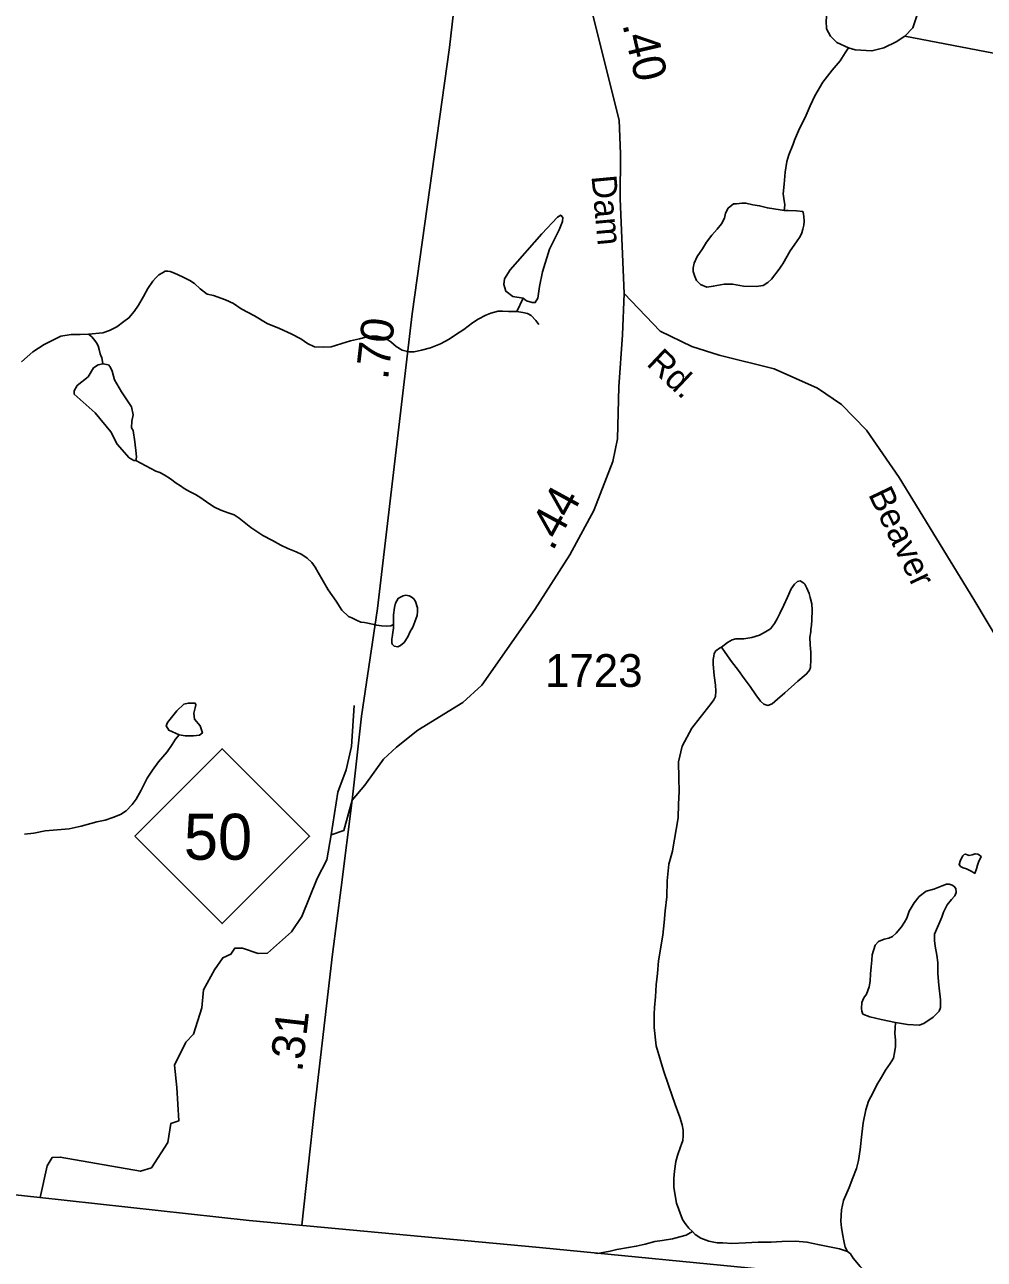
# Model space of a CAD drawing. Extents: x 2056842 to 2160602, y 826753 to 1016856.
# Drawn here: x 2089546 to 2093202, y 846327 to 851032 of the extents above; entities that cross this region are included whole.
import ezdxf

# ---------------------------------------------------------------- set-up
doc = ezdxf.new("R2010")
doc.units = 0
for name, color, linetype in [('Exist Boundary Political CountyLine', 7, 'Continuous'), ('Exist Hydrographic Creek Single Shore', 7, 'Continuous'), ('Exist Hydrographic Misc Water Feature', 7, 'Continuous'), ('Exist Road Non-System Type 51', 7, 'Continuous'), ('Exist Road Primary NC Attributed', 7, 'Continuous'), ('Exist Road Primary NC Service Mileage Hundredths English Label', 7, 'Continuous'), ('Exist Road Primary NC Shield CELL', 7, 'Continuous'), ('Exist Road Primary NC Shield Number Label', 7, 'Continuous'), ('Exist Road Secondary Mileage Hundredths English Label', 7, 'Continuous'), ('Exist Road Secondary Type 20 Attributed', 7, 'Continuous'), ('Exist Road Secondary Type 51 Attributed', 7, 'Continuous'), ('Exist Road Secondary Type 51 Label', 7, 'Continuous'), ('Exist Road Secondary Type 51 Number Label', 7, 'Continuous')]:
    doc.layers.add(name, color=color, linetype=linetype)

msp = doc.modelspace()

# ---------------------------------------------------------------- linework, layer by layer
at = {"layer": 'Exist Boundary Political CountyLine'}
msp.add_lwpolyline([(2087202.4, 846841.6), (2088278.5, 846703.3), (2089060.9, 846620.9), (2089592.9, 846564), (2090401.1, 846475.5), (2091507.2, 846371.9), (2092417.4, 846283.6), (2093037.6, 846221), (2093614.4, 846162.7), (2094823.1, 845562.6), (2096040.2, 844956.3), (2096290.8, 844827.9), (2097736.3, 844110.3), (2098905.5, 843530.6), (2099954.7, 843014.5), (2100389.5, 842806.4), (2101933, 842032.5), (2102162, 841868.8), (2110170.3, 837920.8)], dxfattribs=at)
at = {"layer": 'Exist Hydrographic Creek Single Shore'}
for points in [[(2092899.2, 850987.5), (2093237.1, 850923.1), (2093362.2, 850963.2), (2093719.2, 851313.5), (2093899.2, 851549.4), (2094034.7, 851679.9), (2094262.8, 851850.9)], [(2091421.5, 849938.9), (2091389.1, 849938.6), (2091367, 849940.7), (2091349.6, 849940.5), (2091321.5, 849932.6), (2091303.4, 849924.4), (2091273.5, 849910.2), (2091251.6, 849896.1), (2091219.8, 849870.1), (2091191.7, 849852), (2091163.6, 849834), (2091130, 849816), (2091092, 849799.8), (2091058, 849791.6), (2091029.7, 849785.7), (2091010.2, 849785.5), (2090984, 849791.5), (2090962, 849805.3), (2090941.7, 849823.4), (2090929.8, 849831.3), (2090911.6, 849839.3), (2090889.6, 849845.1), (2090867.5, 849845.2), (2090845.6, 849841.2), (2090821.6, 849835.1), (2090787.5, 849826.9), (2090753.9, 849816.6), (2090729.7, 849808.9), (2090713.7, 849804.8), (2090684, 849802.4), (2090649.9, 849804.3), (2090623.9, 849816.4), (2090597.9, 849834.1), (2090561.8, 849854.2), (2090517.5, 849873.9), (2090469.7, 849893.7), (2090421.3, 849921.8), (2090371.5, 849949.5), (2090341.3, 849969.6), (2090311.4, 849983.4), (2090265.1, 849999.4), (2090241.5, 850005), (2090215.4, 850025.2), (2090193.3, 850045.2), (2090175.2, 850056.8), (2090146.9, 850070.8), (2090117, 850084.7), (2090101, 850090.8), (2090091.2, 850092.7), (2090080.9, 850092.6), (2090070.9, 850086.4), (2090057.3, 850078.4), (2090045, 850066.4), (2090035, 850054.5), (2090015.5, 850026.3), (2089999.5, 849996.2), (2089979.4, 849962.4), (2089963.4, 849938.4), (2089943.7, 849914.2), (2089923.4, 849900.2), (2089897.6, 849880.2), (2089869.9, 849866.1), (2089843.9, 849857.9), (2089789.7, 849851.9)], [(2089789.7, 849851.9), (2089757.8, 849851.5), (2089723.7, 849851.4), (2089683.9, 849845.2), (2089655.8, 849831.2), (2089620, 849813.1), (2089577.9, 849785), (2089534.2, 849747)]]:
    msp.add_lwpolyline(points, dxfattribs=at)
at = {"layer": 'Exist Hydrographic Misc Water Feature'}
msp.add_line((2091444.6, 849989.3), (2091421.5, 849938.9), dxfattribs=at)
for points in [[(2092685, 850943), (2092639.6, 850963.4), (2092615.6, 850987.5), (2092600.4, 851015.4), (2092599.1, 851047), (2092609.2, 851163.6), (2092620.6, 851178.8), (2092647.2, 851187.7), (2092665, 851182.6), (2092711.8, 851156), (2092748.5, 851148.4), (2092785.2, 851148.4), (2092818.2, 851161.1), (2092857.4, 851173.7), (2092894.1, 851172.5), (2092916.9, 851159.8), (2092946, 851116.7), (2092948.6, 851077.5), (2092929.6, 851019.2), (2092899.2, 850987.5)], [(2092899.2, 850987.5), (2092866.3, 850966), (2092819.4, 850943.2), (2092773.8, 850931.8), (2092710.5, 850935.6), (2092685, 850943)], [(2092685, 850943), (2092672, 850924.5), (2092652.5, 850894.6), (2092622.1, 850858.6), (2092586.4, 850812.5), (2092556.5, 850760.2), (2092538.7, 850722.3), (2092519.2, 850678.3), (2092497.3, 850636.1), (2092479.2, 850592.2), (2092473.3, 850576), (2092457.1, 850535.8), (2092449.5, 850509.9), (2092443.5, 850469.8), (2092439.8, 850424.1), (2092435.9, 850387.7), (2092438, 850370), (2092442.1, 850345.8), (2092440, 850323.8)], [(2092440, 850323.8), (2092423.8, 850325.9), (2092375.9, 850333.6), (2092345.7, 850341.8), (2092320.1, 850345.7), (2092293.8, 850351.7), (2092277.6, 850351.2), (2092257.7, 850349.4), (2092245.9, 850349.2), (2092225.8, 850333.2), (2092216.1, 850313.1), (2092212.2, 850295.1), (2092200.1, 850273.4), (2092184.3, 850253), (2092164.2, 850229.3), (2092144.2, 850203.1), (2092128.4, 850177.1), (2092108.5, 850148.9), (2092096.4, 850123.1), (2092092.7, 850105), (2092092.7, 850090.8), (2092098.6, 850072.8), (2092105, 850056.9), (2092121, 850041.1), (2092144.8, 850031), (2092169, 850035.1), (2092211, 850043.3), (2092243, 850043.3), (2092285, 850035.3), (2092333.2, 850033.7), (2092358.8, 850037.9), (2092377.1, 850049.8), (2092390.8, 850061.9), (2092420.6, 850100), (2092430.6, 850115.9), (2092434.7, 850120.2), (2092462.4, 850169.9), (2092486.4, 850204), (2092500.3, 850224.2), (2092506.1, 850238.3), (2092510.2, 850252.3), (2092514.1, 850268.4), (2092516.1, 850282.3), (2092514.3, 850302), (2092511.8, 850316.2), (2092510, 850320.1), (2092486.2, 850322.1), (2092454.2, 850324.1), (2092440, 850323.8)], [(2091444.6, 849989.3), (2091405.4, 849996.5), (2091379.1, 850016.3), (2091371.2, 850041.3), (2091373.8, 850063.7), (2091396.2, 850098), (2091516.1, 850235.1), (2091575.4, 850298.4), (2091588.6, 850306.3), (2091596.5, 850297.1), (2091595.1, 850281.2), (2091582, 850249.6), (2091545.1, 850175.8), (2091518.7, 850090.1), (2091506.9, 850034.7), (2091501.6, 849989.9), (2091491.1, 849972.8), (2091479.2, 849972.8), (2091458.1, 849979.4), (2091444.6, 849989.3)], [(2091505.4, 849888.9), (2091493.7, 849904.9), (2091475.5, 849923), (2091461.3, 849930.9), (2091443.3, 849934.8), (2091421.5, 849938.9)], [(2089844.2, 849739.4), (2089840, 849764), (2089838.1, 849767.9), (2089833.8, 849777.9), (2089830.1, 849793.9), (2089826, 849807.9), (2089820.1, 849819.8), (2089814.1, 849828), (2089802, 849841.9), (2089789.7, 849851.9)], [(2089969.4, 849371.6), (2089961.5, 849371.6), (2089944.4, 849380.9), (2089898.2, 849433.6), (2089874.5, 849479.7), (2089815.2, 849552.2), (2089734.9, 849623.4), (2089734.9, 849636.6), (2089746.7, 849656.4), (2089787.6, 849689.3), (2089808.7, 849723.6), (2089825.8, 849735.5), (2089844.2, 849739.4)], [(2089844.2, 849739.4), (2089865.3, 849735.5), (2089871.9, 849727.6), (2089879.8, 849711.8), (2089889, 849678.8), (2089915.4, 849632.7), (2089953.6, 849576), (2089960.2, 849545.7), (2089954.9, 849520.6), (2089953.6, 849495.6), (2089960.2, 849485), (2089965.4, 849442.8), (2089970.7, 849398), (2089972, 849383.5), (2089969.4, 849371.6)], [(2090950.7, 848745.6), (2090941.1, 848741.3), (2090923.5, 848739.6), (2090905, 848741.5), (2090887.2, 848743.4), (2090859.3, 848749.3), (2090841.2, 848753.3), (2090827.1, 848755), (2090810.9, 848763.1), (2090793.1, 848771.1), (2090779.3, 848776.9), (2090754.7, 848800.8), (2090732.8, 848835), (2090702.6, 848878.5), (2090664.5, 848944.8), (2090652.4, 848964.5), (2090640.5, 848982.5), (2090622.5, 848998.6), (2090602.2, 849012.3), (2090580, 849022.5), (2090548.4, 849036.2), (2090522.2, 849047.9), (2090490, 849066.1), (2090454.1, 849085.8), (2090408.2, 849115.5), (2090363.9, 849151.4), (2090343.8, 849163.4), (2090321.9, 849171.6), (2090293.8, 849181.5), (2090269.8, 849193.3), (2090247.8, 849207.1), (2090217.5, 849229.2), (2090197.4, 849241.1), (2090173.6, 849252.9), (2090153.9, 849264.8), (2090139.4, 849275.1), (2090123.6, 849284.8), (2090101.6, 849300.7), (2090077.4, 849316.6), (2090061.4, 849324.7), (2090045.4, 849330.8), (2089969.4, 849371.6)], [(2092201.2, 848659.5), (2092215.3, 848639.5), (2092239.3, 848605.5), (2092265.5, 848571.4), (2092287.5, 848539.8), (2092309.6, 848509.6), (2092331.6, 848477.9), (2092349.6, 848454.1), (2092361.7, 848442.1), (2092377.5, 848438), (2092393.9, 848444.1), (2092413.8, 848462.2), (2092441.7, 848486.3), (2092491.5, 848530.3), (2092523.5, 848556.3), (2092531.5, 848566.4), (2092535.6, 848572.3), (2092539.3, 848582.7), (2092541.3, 848612.5), (2092541.3, 848640.4), (2092539.1, 848668.3), (2092537, 848698.3), (2092540.7, 848718.4), (2092541.1, 848728.5), (2092543, 848742.4), (2092545, 848764.5), (2092546.7, 848800.3), (2092544.8, 848824.5), (2092538.7, 848848.6), (2092534.4, 848864.6), (2092526.4, 848884.6), (2092518.4, 848900.3), (2092514.3, 848904.2), (2092500.3, 848912.4), (2092490.7, 848910.2), (2092478.4, 848900.3), (2092466.5, 848882.3), (2092452.5, 848850.3), (2092438.6, 848820.3), (2092422.8, 848788.2), (2092412.6, 848768.3), (2092402.7, 848749.9), (2092387.1, 848730), (2092368.9, 848718.1), (2092345.3, 848705.9), (2092316.8, 848696), (2092285.2, 848691.9), (2092254.9, 848691.6), (2092241.1, 848687.6), (2092223.3, 848677.7), (2092205.3, 848663.4), (2092201.2, 848659.5)], [(2090950.7, 848745.6), (2090951, 848731.3), (2090949.1, 848717.4), (2090947.1, 848705.5), (2090945.2, 848689.6), (2090945, 848675.4), (2090947.1, 848669.5), (2090953.4, 848663.6), (2090967.4, 848661.5), (2090977.4, 848665.7), (2090991.3, 848677.8), (2091005.3, 848699.6), (2091014.9, 848719.6), (2091025.2, 848735.9), (2091032.8, 848755.8), (2091041, 848779.8), (2091042.8, 848795.7), (2091043, 848809.9), (2091034.8, 848833.9), (2091028.9, 848843.7), (2091018.6, 848851.8), (2091010.8, 848855.7), (2090998.7, 848857.6), (2090988.7, 848855.4), (2090974.9, 848849.4), (2090968.8, 848845.5), (2090958.9, 848827.5), (2090955.1, 848811.5), (2090950.7, 848783.3), (2090951, 848751.6), (2090950.7, 848745.6)], [(2092201.2, 848659.5), (2092193.2, 848655.5), (2092179.2, 848645.4), (2092173.3, 848635.4), (2092171.2, 848625.5), (2092169.2, 848613.2), (2092169.2, 848595.4), (2092173.3, 848551.3), (2092177.6, 848515.4), (2092179.6, 848491.6), (2092178, 848471.5), (2092171.6, 848459.5), (2092161.6, 848445.2), (2092120, 848391.1), (2092088.2, 848351.2), (2092050.4, 848283.1), (2092036.7, 848223.1), (2092038.8, 848161.1), (2092039, 848109.2), (2092037.3, 848061.1), (2092035.5, 848009.1), (2092027.7, 847964.8), (2092015.8, 847890.7), (2092013.5, 847882.9), (2091999.8, 847833.1), (2091993.6, 847768.7), (2091992.2, 847708.9), (2091986.3, 847655), (2091982.4, 847611), (2091976.8, 847562.7), (2091961, 847464.9), (2091957.1, 847416.8), (2091951.2, 847372.7), (2091949.4, 847326.7), (2091945.3, 847286.7), (2091943.6, 847261), (2091943.6, 847210.7), (2091952, 847140.8), (2091980.1, 847046.9), (2092000.4, 846987.1), (2092024.8, 846917.2), (2092042.6, 846869.1), (2092051.1, 846839.4), (2092054.7, 846819.3), (2092055, 846797.4), (2092053.3, 846779.4), (2092048.8, 846765.4), (2092044.9, 846755.1), (2092033.2, 846723.2), (2092027.3, 846699.4), (2092021.1, 846663.3), (2092019.5, 846635.2), (2092019.3, 846601.2), (2092029.7, 846541.1), (2092051.7, 846479.4), (2092062.3, 846463.2), (2092076.3, 846445.2), (2092090.4, 846433.4)], [(2090134.6, 848325.2), (2090095.8, 848343.3), (2090085.2, 848360.5), (2090090.5, 848372.3), (2090126.1, 848417.2), (2090152.4, 848442.2), (2090169.5, 848446.2), (2090195.9, 848446.2), (2090198.5, 848439.6), (2090195.9, 848429), (2090190.6, 848407.9), (2090193.3, 848385.5), (2090214.3, 848360.5), (2090223.6, 848332.8), (2090211.7, 848324.9), (2090189.3, 848322.2), (2090157.7, 848322.2), (2090134.6, 848325.2)], [(2090134.6, 848325.2), (2090120.5, 848309.1), (2090108.6, 848288.9), (2090088.5, 848260.7), (2090056.7, 848223), (2090033.1, 848190.8), (2090013.2, 848160.6), (2089989.5, 848114.7), (2089971, 848080.6), (2089955.4, 848060.6), (2089933.5, 848036.3), (2089911.5, 848022.2), (2089881.6, 848010.1), (2089853.5, 848000.2), (2089821.5, 847994.1), (2089797.9, 847987.9), (2089761.9, 847977.9), (2089715.5, 847967.9), (2089669.8, 847963.5), (2089624.1, 847959.5), (2089581.8, 847951.3), (2089545.5, 847947.4)], [(2093165.7, 847796.8), (2093153.8, 847804.7), (2093133.9, 847814.6), (2093121.6, 847818.5), (2093111.6, 847824.4), (2093105.8, 847832.2), (2093111.4, 847848.4), (2093119.6, 847864.2), (2093125.7, 847870.2), (2093129.6, 847870.4), (2093143.8, 847866.3), (2093155.5, 847868.5), (2093167.4, 847872.4), (2093177.6, 847870.5), (2093187.7, 847864.5), (2093189.5, 847860.5), (2093181.3, 847844.7), (2093175.8, 847828.5), (2093171.7, 847814.5), (2093165.7, 847796.8)], [(2092863.5, 847229.5), (2092909.8, 847221.7), (2092953.7, 847219.9), (2092971.7, 847226.1), (2093007.6, 847250.3), (2093029.4, 847272.1), (2093035.3, 847286.3), (2093035.1, 847316.3), (2093029.2, 847372), (2093025.1, 847416), (2093024.8, 847458.3), (2093021, 847486.1), (2093014.6, 847520.2), (2093012.3, 847542.1), (2093012.1, 847566.1), (2093040.2, 847630.4), (2093046.2, 847650.2), (2093060.1, 847678.1), (2093076.3, 847698.4), (2093090.1, 847712.5), (2093094.2, 847724.5), (2093093.7, 847740.3), (2093085.7, 847748.4), (2093080, 847752.2), (2093067.5, 847756.1), (2093057.9, 847756.4), (2093041.9, 847750.2), (2093009.7, 847738.1), (2092979.9, 847730), (2092954.1, 847710), (2092934, 847685.9), (2092916.2, 847653.6), (2092906.3, 847627.5), (2092898.1, 847611.8), (2092886.2, 847593.7), (2092866.5, 847569.5), (2092852.6, 847557.8), (2092838.5, 847551.4), (2092820.8, 847547.6), (2092798.3, 847537.6), (2092786.6, 847523.6), (2092774.7, 847487.2), (2092773, 847467.2), (2092770.8, 847441.6), (2092768.9, 847415.5), (2092766.9, 847387.4), (2092763.2, 847365.2), (2092753.2, 847337.5), (2092743.5, 847323.2), (2092735.3, 847305.3), (2092733.5, 847283.3), (2092735.1, 847273.3), (2092739.6, 847261.3), (2092765.5, 847251.3), (2092809.3, 847241.4), (2092863.5, 847229.5)], [(2092863.5, 847229.5), (2092861.8, 847209.5), (2092861.6, 847187.6), (2092863.5, 847163.8), (2092863.9, 847137.8), (2092859.8, 847113.6), (2092855.7, 847093.6), (2092843.8, 847073.8), (2092825.9, 847047.8), (2092810.2, 847021.8), (2092792.3, 846991.6), (2092778.4, 846963.3), (2092760.3, 846929.5), (2092750.3, 846897.3), (2092740.6, 846847.3), (2092735.1, 846803.5), (2092728.8, 846745.2), (2092723, 846703.4), (2092715.2, 846673.4), (2092701.5, 846637.3), (2092687.3, 846601.3), (2092665.4, 846551.1), (2092657.8, 846515.3), (2092655.8, 846473), (2092657.8, 846447.2), (2092662.3, 846417.3), (2092666.2, 846397.2), (2092672.4, 846373.1), (2092680.4, 846357.3)], [(2091722.6, 846350.5), (2091729.9, 846349.8), (2091742.5, 846352.2), (2091776.7, 846358.4), (2091802.3, 846364.6), (2091846.2, 846372.6), (2091876.1, 846376.6), (2091910.2, 846384.8), (2091946.3, 846394.7), (2091974.2, 846399), (2092014.4, 846405.1), (2092042.4, 846413), (2092066.4, 846419.1), (2092090.4, 846433.4)], [(2092090.4, 846433.4), (2092100.3, 846421.3), (2092122.2, 846407.4), (2092152.1, 846395.6), (2092184.3, 846389.5), (2092206.1, 846389.8), (2092240.1, 846387.9), (2092292.4, 846390.2), (2092340.2, 846392.3), (2092390.4, 846392.4), (2092430.2, 846394.4), (2092482.1, 846396.7), (2092526, 846392.9), (2092574.1, 846382.8), (2092650, 846367.2), (2092680.4, 846357.3)], [(2092680.4, 846357.3), (2092692.3, 846347.4), (2092702.3, 846331.3), (2092728.5, 846299.3), (2092746.2, 846283.6), (2092754.6, 846277.5), (2092766.3, 846271.7), (2092776.7, 846269.7), (2092788.6, 846267.5), (2092814.5, 846269.6), (2092828.4, 846271.6), (2092854.5, 846279.8), (2092876.4, 846283.8), (2092890.3, 846284.1), (2092902.4, 846281.9), (2092918.4, 846274.1), (2092938.7, 846260.1), (2093002, 846224.6)]]:
    msp.add_lwpolyline(points, dxfattribs=at)
at = {"layer": 'Exist Road Non-System Type 51'}
for points in [[(2090714.3, 847945.1), (2090739.2, 848107.2), (2090770.4, 848192.4), (2090791.2, 848281.8), (2090801.6, 848437.7)], [(2090793.8, 848076.9), (2090762.1, 847961.7), (2090714.3, 847945.1)], [(2090714.3, 847945.1), (2090697.7, 847849.5), (2090660.3, 847778.8), (2090602.2, 847633.3), (2090562.7, 847575.1), (2090471.3, 847494), (2090436, 847492), (2090375.8, 847512.7), (2090346.7, 847512.7), (2090332.1, 847489.9), (2090301, 847475.3), (2090268.8, 847430.7), (2090227.3, 847353.7), (2090221, 847285.2), (2090189.9, 847185.4), (2090160.8, 847154.2), (2090117.2, 847066.9), (2090125.5, 846981.7), (2090133.8, 846854.9), (2090102.6, 846844.5), (2090091.2, 846772.8), (2090028.9, 846675.1), (2089987.4, 846662.7), (2089682, 846716.7), (2089650.9, 846714.6), (2089632.2, 846683.5), (2089605, 846562.7)]]:
    msp.add_lwpolyline(points, dxfattribs=at)
at = {"layer": 'Exist Road Primary NC Attributed'}
for points in [[(2090793.8, 848076.9), (2090829.9, 848397.1), (2090890.1, 848806.6), (2090995, 849693), (2091022, 849929.9), (2091164.2, 850945.2), (2091222.4, 851456.5), (2091255.4, 851735.3)], [(2090601.9, 846456.7), (2090650.2, 846899.7), (2090718.7, 847489.9), (2090752, 847743.5), (2090793.8, 848076.9)]]:
    msp.add_lwpolyline(points, dxfattribs=at)
at = {"layer": 'Exist Road Primary NC Shield CELL'}
msp.add_lwpolyline([(2089965.4, 847939.5), (2090298.4, 848272.5), (2090631.4, 847939.5), (2090298.4, 847606.5)], close=True, dxfattribs=at)
at = {"layer": 'Exist Road Secondary Type 20 Attributed'}
msp.add_lwpolyline([(2090793.8, 848076.9), (2090842.6, 848134), (2090913.2, 848232.8), (2090963.1, 848278.5), (2091043.5, 848343.4), (2091215.9, 848448.4), (2091287.6, 848514.9), (2091489.5, 848803.3), (2091622.5, 849011.1), (2091714.4, 849180), (2091787.1, 849367), (2091804.7, 849453.3), (2091809.4, 849652.3), (2091823.9, 849849.7), (2091830.2, 850007.7)], dxfattribs=at)
at = {"layer": 'Exist Road Secondary Type 51 Attributed'}
for points in [[(2091255.4, 851735.3), (2091303.1, 851722.8), (2091404.9, 851679.2), (2091506.7, 851600.2), (2091585.6, 851504.6), (2091611.6, 851441.2), (2091692.6, 851141.9), (2091786, 850767.8), (2091810.9, 850668.1), (2091816.1, 850540.2), (2091814.6, 850368.3), (2091822.9, 850187.4), (2091830.2, 850007.7)], [(2091830.2, 850007.7), (2091967.2, 849864.3), (2092087.7, 849806.1), (2092191.5, 849772.8), (2092401.3, 849720.9), (2092566.4, 849647.1), (2092657.8, 849584.7), (2092753.3, 849487), (2092878, 849306.2), (2093161.5, 848841.7), (2093311, 848592.3), (2093419, 848399), (2093507.3, 848067.5), (2093594.5, 847762), (2093636, 847589.5), (2093648.5, 847479.4), (2093630.8, 847339.1), (2093589.3, 847141.6), (2093558.1, 846948.3), (2093536.3, 846683.4), (2093536.3, 846508.8), (2093550.9, 846434), (2093580, 846348.7)]]:
    msp.add_lwpolyline(points, dxfattribs=at)

# ---------------------------------------------------------------- texts
at = {"layer": 'Exist Road Primary NC Service Mileage Hundredths English Label'}
for s, rotation, p in [('.70', 83.4989, (2090930.2, 849676.2)), ('.31', 83.3766, (2090603.3, 847038))]:
    msp.add_text(s, height=125, rotation=rotation, dxfattribs=at).set_placement(p)
at = {"layer": 'Exist Road Primary NC Shield Number Label'}
msp.add_text('50', height=175, dxfattribs=at).set_placement((2090152.6, 847849.8))
at = {"layer": 'Exist Road Secondary Mileage Hundredths English Label'}
for s, rotation, p in [('.40', 283.1109, (2091822.5, 851033.3)), ('.44', 61.4433, (2091557.7, 849022.9))]:
    msp.add_text(s, height=125, rotation=rotation, dxfattribs=at).set_placement(p)
at = {"layer": 'Exist Road Secondary Type 51 Label'}
for s, rotation, p in [('Dam', 275.3147, (2091705.1, 850454.6)), ('Rd.', 316.5979, (2091911.3, 849736.6)), ('Beaver', 295.6861, (2092758.3, 849242.2))]:
    msp.add_text(s, height=95, rotation=rotation, dxfattribs=at).set_placement(p)
at = {"layer": 'Exist Road Secondary Type 51 Number Label'}
msp.add_text('1723', height=125, dxfattribs=at).set_placement((2091528.2, 848508.2))

doc.saveas('drawing.dxf')
